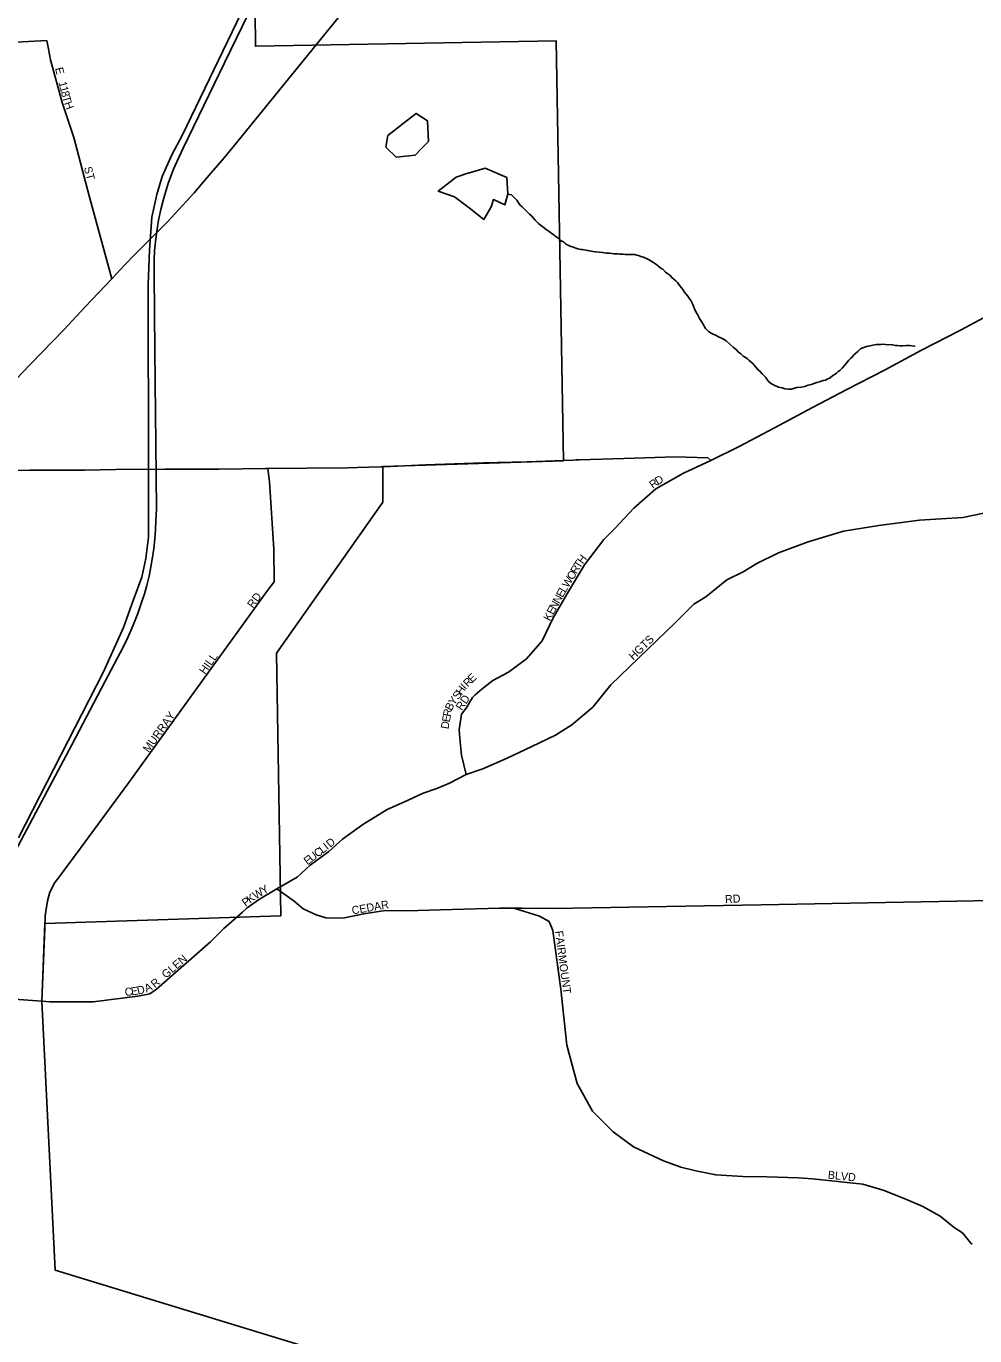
# Model space of a CAD drawing. Extents: x 2139079 to 2262683, y 1235796 to 1334992.
# Drawn here: x 2214145 to 2220073, y 1274064 to 1282247 of the extents above; entities that cross this region are included whole.
import ezdxf

# ---------------------------------------------------------------- set-up
doc = ezdxf.new("R2010")
doc.units = 0
for name, color, linetype in [('GM_X_City_Street', 7, 'Continuous'), ('GM_X_City_Street_Text', 7, 'Continuous'), ('GM_X_Interstate_Route', 7, 'Continuous'), ('GM_X_Minor_Lake', 7, 'Continuous'), ('GM_X_Minor_River', 7, 'Continuous'), ('GM_X_Rail_Line', 7, 'Continuous'), ('GM_X_US_Route', 7, 'Continuous')]:
    doc.layers.add(name, color=color, linetype=linetype)

msp = doc.modelspace()

# ---------------------------------------------------------------- linework, layer by layer
at = {"layer": 'GM_X_City_Street'}
for points in [[(2209270.3, 1282037), (2209270.3, 1282037), (2210013.1, 1282051.4), (2210522.2, 1282061.3), (2210862.8, 1282067.9), (2211729.6, 1282084.6), (2212480.7, 1282108.6), (2213159.1, 1282132.6), (2213813.3, 1282132.4), (2214273.8, 1282156.6), (2214283.9, 1282105.5)], [(2214283.9, 1282105.5), (2214284.3, 1282103.9), (2214297.9, 1282035.4), (2214370.5, 1281768.8), (2214443, 1281550.8), (2214539.9, 1281187.3), (2214679.8, 1280669)], [(2216951.1, 1278068.7), (2216993.6, 1278105.8), (2217061.4, 1278158.5), (2217159.4, 1278211.3), (2217272.4, 1278294.1), (2217370.5, 1278407.1), (2217438.3, 1278550.2), (2217521.3, 1278693.3), (2217634.3, 1278881.7), (2217754.9, 1279039.8), (2217822.8, 1279107.5), (2217943.3, 1279235.6), (2218079.1, 1279356.1), (2218252.3, 1279454), (2218424, 1279532.2)], [(2214333.6, 1276907.9), (2214334.4, 1276909), (2214484.2, 1277111.5), (2214786.4, 1277520.8), (2215653.6, 1278721.6), (2215694.3, 1278774.8), (2215693, 1278979.6), (2215666.1, 1279400.4), (2215656.1, 1279483.3)], [(2216895.5, 1277571), (2216999, 1277606.5), (2217151.5, 1277674.2), (2217304.1, 1277746.2), (2217452.3, 1277818.1), (2217554, 1277881.6), (2217685.3, 1277991.7), (2217799.6, 1278131.4), (2217973.4, 1278300.7), (2218202.1, 1278520.9), (2218316.6, 1278635.2), (2218392.8, 1278681.7), (2218524.1, 1278787.6), (2218625.8, 1278838.4), (2218710.5, 1278889.1), (2218846.1, 1278956.9), (2219032.4, 1279024.6), (2219252.7, 1279092.3), (2219473, 1279126), (2219727.1, 1279159.8), (2219998.1, 1279176.6), (2220320, 1279244.4)], [(2216895.5, 1277571), (2216865.3, 1277691.5), (2216857.9, 1277774.5), (2216850.4, 1277849.7), (2216865.4, 1277947.7), (2216895.7, 1277985.4), (2216933.3, 1278053.1), (2216951.1, 1278068.7)], [(2216471.1, 1277383.9), (2216472.2, 1277384.4), (2216533.1, 1277411.8), (2216626.3, 1277454.3), (2216711, 1277483.8), (2216791.4, 1277517.7), (2216895.5, 1277571)], [(2215711.3, 1276857.4), (2215838.4, 1276929.4), (2215918.9, 1277005.5), (2216037.5, 1277090.2), (2216122.2, 1277166.4), (2216249.3, 1277259.6), (2216401.8, 1277352.7), (2216471.1, 1277383.9)], [(2214242.7, 1276154.3), (2214262.5, 1276612), (2214264.5, 1276688.3), (2214278.1, 1276783), (2214292.8, 1276835.6), (2214325.3, 1276896.7), (2214333.6, 1276907.9)], [(2215498.9, 1276713.9), (2215527.1, 1276738.8), (2215602.9, 1276793.3), (2215711.3, 1276857.4)], [(2215711.3, 1276857.4), (2215820.1, 1276780.8), (2215875.5, 1276732.1), (2215956.7, 1276694), (2216017.4, 1276675.5), (2216123.7, 1276674.3), (2216255.3, 1276699.8), (2216389.1, 1276721.3), (2216523.5, 1276718.8), (2216733.9, 1276726.2), (2217102.6, 1276735.8), (2217192.7, 1276735.4), (2217241.2, 1276735.2), (2217242.5, 1276735.2)], [(2217242.5, 1276735.2), (2217441.5, 1276734.5), (2218738.2, 1276756.1), (2220626.1, 1276793), (2224622.9, 1276842.2)], [(2214360.8, 1276150.8), (2214563.2, 1276151.5), (2214843, 1276186.7), (2214917.1, 1276201.4), (2214959.4, 1276229.6), (2215296.1, 1276525.6), (2215380.7, 1276610.1), (2215496.3, 1276711.7), (2215498.9, 1276713.9)], [(2217192.7, 1276735.4), (2217353, 1276686.1), (2217413.1, 1276652.7), (2217436.5, 1276596.8), (2217488.6, 1276213), (2217491, 1276191.2), (2217491.1, 1276190)], [(2213337.5, 1276214.1), (2213382.1, 1276220.8), (2213419.2, 1276226.5), (2213896.2, 1276179.9), (2214242.7, 1276154.3), (2214292.4, 1276150.6), (2214344.4, 1276150.8), (2214360.8, 1276150.8)], [(2217491.1, 1276190), (2217524.4, 1275880.7), (2217587.6, 1275640.3), (2217684.5, 1275467.4), (2217813.1, 1275338.1), (2217940.4, 1275245.9), (2218127.7, 1275157.7), (2218236.8, 1275117.2), (2218329.6, 1275096.1), (2218454.4, 1275069.5), (2218622.4, 1275059.4), (2218772.9, 1275058.3), (2218971.8, 1275050.7), (2219059, 1275045.3), (2219372.3, 1275011.6), (2219506, 1274971.8), (2219646.2, 1274916.2), (2219747.9, 1274871.3), (2219856.1, 1274812.6), (2219943.6, 1274741.8), (2219995, 1274707.6), (2220048, 1274644.2), (2220055.4, 1274636.1)]]:
    msp.add_lwpolyline(points, dxfattribs=at)
at = {"layer": 'GM_X_Interstate_Route'}
msp.add_lwpolyline([(2217343, 1291091.3), (2217395.8, 1287451.7), (2215979.9, 1287405.4), (2215797.6, 1287404.4), (2215527.1, 1287430.9), (2215577.3, 1282121.1), (2217456.1, 1282156), (2217503, 1279531.3), (2216373.5, 1279494.7), (2216374.8, 1279272.1), (2215709.1, 1278329.8), (2215736.5, 1276687.6), (2214262.5, 1276641.1), (2214242.7, 1276154.3), (2214327.4, 1274473.5), (2216930.9, 1273680)], dxfattribs=at)
at = {"layer": 'GM_X_Minor_Lake'}
for points in [[(2216406.2, 1281564.1), (2216519.9, 1281653.3)], [(2216519.9, 1281653.3), (2216582.1, 1281702.1), (2216653.4, 1281655.3), (2216660, 1281526.8), (2216615.8, 1281481.9)], [(2216615.8, 1281481.9), (2216575.4, 1281440.8), (2216457.2, 1281428.5), (2216393.7, 1281491.5), (2216406.2, 1281564.1)], [(2216832.1, 1281302.8), (2216720.6, 1281216.6), (2216821.7, 1281180.4), (2216913.5, 1281111.9), (2217005.3, 1281039.4), (2217049.9, 1281118.6), (2217065, 1281163.1), (2217136, 1281130.3), (2217154.7, 1281196.9), (2217148.6, 1281301.3), (2217012.8, 1281358.9), (2216915, 1281330.9)], [(2216911.4, 1281329.7), (2216832.1, 1281302.8)], [(2216915, 1281330.9), (2216911.4, 1281329.7)]]:
    msp.add_lwpolyline(points, dxfattribs=at)
at = {"layer": 'GM_X_Minor_River'}
for points in [[(2217154.7, 1281196.9), (2217178.9, 1281193.4), (2217211.7, 1281159.9), (2217230.4, 1281130.1), (2217244.7, 1281118.3), (2217254.9, 1281108.5), (2217263.1, 1281098.6), (2217273.4, 1281088.8), (2217289.8, 1281073), (2217302.1, 1281061.2), (2217314.4, 1281047.4), (2217326.7, 1281035.6), (2217337, 1281023.7), (2217347.2, 1281013.9), (2217361.5, 1281002.1), (2217371.7, 1280994.2), (2217383.9, 1280984.4), (2217396.2, 1280974.6), (2217410.4, 1280964.9), (2217424.7, 1280955.1), (2217436.9, 1280947.3), (2217447.1, 1280939.5), (2217457.3, 1280929.6), (2217467.5, 1280923.8), (2217481.8, 1280910), (2217492, 1280904.2), (2217502.2, 1280898.3), (2217512.4, 1280888.5), (2217526.6, 1280880.7), (2217536.7, 1280876.9), (2217548.9, 1280871.1), (2217559, 1280867.3), (2217569.1, 1280863.5), (2217579.3, 1280859.7), (2217591.4, 1280855.9), (2217609.5, 1280852.2), (2217621.6, 1280850.4), (2217631.7, 1280848.6), (2217643.8, 1280846.9), (2217653.9, 1280845), (2217665.9, 1280843.3), (2217676, 1280841.4), (2217686.1, 1280839.6), (2217704.2, 1280836), (2217746.5, 1280832.8), (2217758.6, 1280831), (2217770.6, 1280829.2), (2217790.8, 1280827.6), (2217804.9, 1280825.9), (2217816.9, 1280824.1), (2217827, 1280824.3), (2217841, 1280824.6), (2217853.1, 1280822.8), (2217863.1, 1280823), (2217875.2, 1280821.2), (2217887.3, 1280819.4), (2217899.4, 1280819.7), (2217911.4, 1280819.9), (2217929.5, 1280820.2), (2217939.5, 1280820.4), (2217949.5, 1280820.6), (2217959.6, 1280816.8), (2217971.8, 1280813), (2217986, 1280807.3), (2218000.1, 1280803.5), (2218016.3, 1280797.8), (2218034.5, 1280788.1), (2218044.7, 1280782.3), (2218077.3, 1280760.8), (2218087.5, 1280753), (2218097.7, 1280745.2), (2218114, 1280733.4), (2218124.1, 1280727.6), (2218140.6, 1280709.8), (2218154.8, 1280700.1), (2218167.1, 1280690.3), (2218179.4, 1280676.4), (2218193.7, 1280664.7), (2218203.9, 1280654.8), (2218214.2, 1280645), (2218224.5, 1280633.1), (2218232.7, 1280623.2), (2218241, 1280611.3), (2218249.2, 1280601.5), (2218257.5, 1280587.6), (2218267.8, 1280573.7), (2218280.2, 1280559.9), (2218288.4, 1280548), (2218298.8, 1280532.1), (2218305.1, 1280520.2), (2218311.3, 1280508.3), (2218326.2, 1280470.4), (2218340.7, 1280444.6), (2218353.3, 1280420.7), (2218365.7, 1280400.8), (2218376.1, 1280385), (2218382.4, 1280373), (2218390.7, 1280357.1), (2218411.2, 1280337.4), (2218429.5, 1280325.8), (2218455.9, 1280314.2)], [(2218455.9, 1280314.2), (2218472.1, 1280306.5), (2218486.3, 1280298.7), (2218502.5, 1280291), (2218518.8, 1280281.3), (2218565.8, 1280240), (2218582.1, 1280226.3), (2218596.5, 1280210.5), (2218610.8, 1280198.7), (2218625.2, 1280184.9), (2218643.4, 1280175.2), (2218653.6, 1280167.4), (2218663.9, 1280157.5), (2218676.1, 1280147.7), (2218686.3, 1280139.9), (2218694.6, 1280128), (2218706.9, 1280114.2), (2218719.3, 1280100.4), (2218731.6, 1280088.5), (2218743.9, 1280074.7), (2218754.1, 1280064.9), (2218766.5, 1280051.1), (2218772.7, 1280041.1), (2218785.1, 1280025.3), (2218803.4, 1280011.6), (2218823.7, 1280001.9), (2218846, 1279992.3), (2218868.2, 1279986.7), (2218886.4, 1279981.1), (2218908.5, 1279979.5), (2218926.5, 1279979.8), (2218940.5, 1279982.1), (2218960.5, 1279988.5), (2218988.6, 1279991.1), (2219010.6, 1279995.5), (2219032.5, 1280004), (2219052.5, 1280008.4), (2219066.4, 1280014.7), (2219086.3, 1280021.1), (2219102.3, 1280025.4), (2219112.3, 1280029.6), (2219126.3, 1280031.9), (2219140.3, 1280034.2), (2219150.2, 1280040.4), (2219168.1, 1280048.8), (2219185.8, 1280065.2), (2219199.8, 1280071.5), (2219209.6, 1280079.7), (2219219.5, 1280090), (2219229.4, 1280096.2), (2219243.2, 1280110.5), (2219258.9, 1280126.9), (2219286.3, 1280159.6), (2219296.2, 1280169.8), (2219306, 1280178), (2219315.8, 1280190.3), (2219329.6, 1280204.6), (2219341.4, 1280214.9), (2219359.2, 1280231.3), (2219373.1, 1280237.6), (2219389, 1280243.9), (2219405, 1280248.2), (2219419, 1280250.5), (2219435, 1280252.8), (2219447, 1280255.1), (2219459, 1280257.3), (2219471.1, 1280257.6), (2219485.1, 1280257.8), (2219499.1, 1280260.1), (2219515.2, 1280258.4), (2219535.3, 1280256.8), (2219549.4, 1280257.1), (2219559.5, 1280255.2), (2219575.6, 1280251.6), (2219589.7, 1280251.8), (2219603.8, 1280250.1), (2219623.8, 1280250.5), (2219645.9, 1280250.9), (2219664, 1280251.2), (2219680.1, 1280249.6), (2219696.2, 1280247.8), (2219698.2, 1280247.9), (2219700.1, 1280249.9)]]:
    msp.add_lwpolyline(points, dxfattribs=at)
at = {"layer": 'GM_X_Rail_Line'}
for points in [[(2214005.8, 1276956.6), (2214240.8, 1277400.3), (2214429.9, 1277756.7), (2214637.2, 1278149.6), (2214716.4, 1278299.4), (2214748.3, 1278361.7), (2214780.1, 1278427.4), (2214814, 1278504), (2214842.4, 1278577.1), (2214864.8, 1278638.8), (2214884.4, 1278701.1), (2214898.7, 1278752.6), (2214912.9, 1278810.9), (2214924.4, 1278869.8), (2214933.2, 1278915.9), (2214943.4, 1278983.6), (2214949.5, 1279043.2), (2214953.5, 1279102.2), (2214956.3, 1279156.4), (2214959.6, 1279231.6), (2214956.3, 1279636.7), (2214952.2, 1280020.8), (2214948.1, 1280440.2), (2214944.7, 1280712.5), (2214946.1, 1280785.7), (2214948.1, 1280844), (2214954.9, 1280918.5), (2214965.7, 1280992.3), (2214972.5, 1281033.7), (2214986.1, 1281101.4), (2215001, 1281157.6), (2215017.2, 1281216.6), (2215033.5, 1281263.3), (2215049.7, 1281310.1), (2215066.7, 1281354.1), (2215087, 1281398.8), (2215127, 1281485.5), (2215385.1, 1282018), (2215609.3, 1282482.8)], [(2214098.2, 1277175.5), (2214627.7, 1278213.7), (2214754, 1278490.5), (2214814.2, 1278659), (2214868.3, 1278803.5), (2214892.4, 1278920.8), (2214910.4, 1279053.2), (2214910.4, 1279465.5), (2214907.4, 1280633), (2214916.4, 1280846.7), (2214931.5, 1281054.3), (2214961.6, 1281195.8), (2214994.6, 1281307.1), (2215054.8, 1281442.5), (2215121, 1281562.9), (2215545.1, 1282447.6)]]:
    msp.add_lwpolyline(points, dxfattribs=at)
at = {"layer": 'GM_X_US_Route'}
for points in [[(2215958, 1282130.5), (2216140.2, 1282354.2), (2216351.9, 1282639.3)], [(2215025.9, 1281023), (2215051.4, 1281048.8), (2215076.4, 1281076.3), (2215194.4, 1281206.2), (2215299.6, 1281327.3), (2215383, 1281424.2), (2215468.3, 1281529.1), (2215958, 1282130.5)], [(2214762.6, 1280755.5), (2214817.6, 1280812.9), (2214824.8, 1280820.5), (2215025.9, 1281023)], [(2213553.3, 1279463.5), (2213553.3, 1279463.5), (2213586.8, 1279500.2), (2213750, 1279679.5), (2213944.6, 1279893.5), (2214115.5, 1280077.2), (2214240.7, 1280206.5), (2214381.7, 1280351.9), (2214514.9, 1280493.3), (2214679.8, 1280669), (2214762.6, 1280755.5)], [(2218424, 1279532.2), (2218599.7, 1279619.8), (2218821.2, 1279737.7), (2219058.7, 1279863.8), (2219274.2, 1279975.8), (2219507.7, 1280097.8), (2219739.2, 1280221.9), (2219986.7, 1280350.1), (2220157.6, 1280440.7)], [(2216363.7, 1279492.7), (2216377.3, 1279493.4), (2216640.1, 1279506.8), (2217000.8, 1279517.5), (2217273.4, 1279525.6), (2217564, 1279535.8), (2217582.5, 1279536.4)], [(2217582.5, 1279536.4), (2217601.1, 1279537), (2217882.6, 1279546.2), (2218203.3, 1279556.6), (2218405.6, 1279549.1), (2218424, 1279532.2)], [(2213553.3, 1279463.5), (2213864, 1279465.8), (2214168.7, 1279472.1), (2214242.7, 1279472)], [(2214242.7, 1279472), (2214413.3, 1279471.9), (2214510.8, 1279473.3), (2214705.9, 1279476.1), (2215012.6, 1279478.4), (2215351.4, 1279479), (2215640, 1279483.2), (2215656.1, 1279483.3), (2215898.6, 1279485.1), (2216155.1, 1279487.1), (2216214.9, 1279488.6), (2216361.6, 1279492.6), (2216363.7, 1279492.7)]]:
    msp.add_lwpolyline(points, dxfattribs=at)

# ---------------------------------------------------------------- texts
at = {"layer": 'GM_X_City_Street_Text'}
for s, rotation, p in [('E', 284.0491, (2214325.3, 1281983)), ('1', 284.1271, (2214347.3, 1281894.9)), ('1', 284.09682, (2214354.8, 1281865.1)), ('8', 284.12909, (2214362.3, 1281835.2)), ('T', 285.70546, (2214370.2, 1281803.9)), ('H', 290.25077, (2214381.1, 1281765.8)), ('ST', 284.93778, (2214505.6, 1281362.7)), ('R', 35.85952, (2218061.1, 1279354.7)), ('D', 31.36117, (2218092.3, 1279377.4)), ('R', 58.78222, (2217584.9, 1278820.3)), ('T', 57.91642, (2217605.3, 1278854)), ('H', 53.17382, (2217623.4, 1278882.9)), ('W', 58.78246, (2217532.4, 1278733.7)), ('O', 58.78193, (2217562.1, 1278782.7)), ('RD', 53.7411, (2215562.6, 1278607)), ('E', 60.67201, (2217497.4, 1278673.2)), ('L', 59.22833, (2217514.5, 1278703.6)), ('E', 61.59009, (2217438.6, 1278565.2)), ('N', 61.37209, (2217455.3, 1278596.1)), ('N', 61.35291, (2217476.4, 1278634.7)), ('K', 62.58452, (2217418.4, 1278526.3)), ('HGTS', 44.14704, (2217939.3, 1278282.4)), ('HILL', 54.78467, (2215263.3, 1278193.3)), ('I', 46.57655, (2216890.4, 1278098.3)), ('R', 45, (2216905.3, 1278114)), ('E', 45, (2216933.3, 1278142)), ('Y', 54.51566, (2216820, 1277999.4)), ('S', 54.4909, (2216845.6, 1278035.2)), ('H', 54.52942, (2216866, 1278063.9)), ('RD', 55.49205, (2216866.8, 1277967.7)), ('MURRAY', 54.46232, (2214911.3, 1277705)), ('R', 79.69374, (2216798, 1277930.1)), ('B', 64.19522, (2216803.9, 1277965.7)), ('D', 79.69319, (2216783.8, 1277852.2)), ('E', 79.69317, (2216791.7, 1277895.5)), ('D', 40.17373, (2216045.1, 1277111.9)), ('U', 37.21859, (2215931.3, 1277024.3)), ('C', 37.21472, (2215966.3, 1277050.9)), ('L', 37.58353, (2215998.2, 1277075.1)), ('I', 38.98589, (2216027.1, 1277097.4)), ('E', 37.20873, (2215903.3, 1277003)), ('K', 35.76409, (2215544.8, 1276764.1)), ('W', 32.37964, (2215579.9, 1276789.3)), ('Y', 30.48771, (2215627.8, 1276819.7)), ('P', 35.74413, (2215516.2, 1276743.5)), ('CEDAR', 9.86701, (2216184.2, 1276696.7)), ('RD', 3.01158, (2218513.3, 1276767.3)), ('FAIRMOUNT', 277.5479, (2217449.5, 1276591.9)), ('GLEN', 40.60001, (2215018.4, 1276294.2)), ('D', 12.57055, (2214843.7, 1276196.3)), ('A', 24.19345, (2214897.1, 1276209.4)), ('R', 39.48301, (2214949.6, 1276235.1)), ('C', 6.86592, (2214764, 1276186.5)), ('E', 6.84711, (2214803.3, 1276191.2)), ('BLVD', 353.99399, (2219152.7, 1275046.8))]:
    msp.add_text(s, height=50, rotation=rotation, dxfattribs=at).set_placement(p)

doc.saveas('drawing.dxf')
